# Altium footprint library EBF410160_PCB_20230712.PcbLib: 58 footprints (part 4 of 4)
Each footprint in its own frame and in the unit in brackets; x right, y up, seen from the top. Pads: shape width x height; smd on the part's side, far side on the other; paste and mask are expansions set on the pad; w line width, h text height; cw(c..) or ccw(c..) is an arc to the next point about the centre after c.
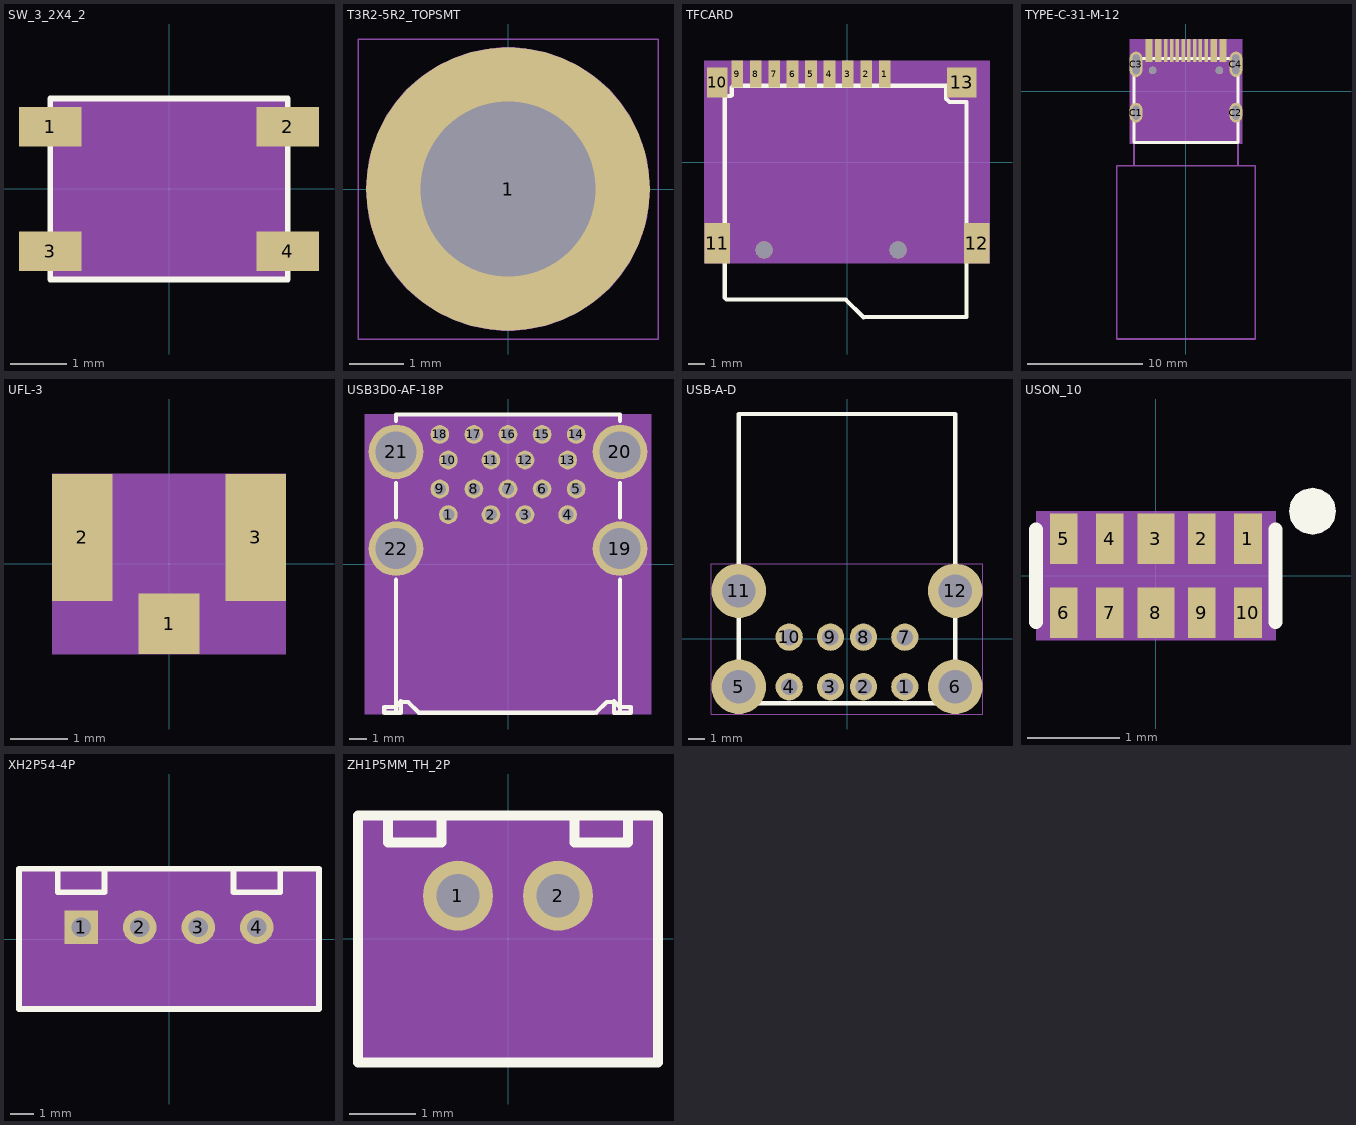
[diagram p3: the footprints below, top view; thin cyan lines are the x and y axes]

## SW_3_2X4_2 [mil] "SW_3_2X4_2"
pads (4):
  rect 43.31x27.56 smd: 1(-82.97,43) 2(82.39,43) 3(-82.97,-43.62) 4(82.39,-43.62)
Top Overlay:
  lines w3.94: -82.97,-63.3 -82.97,62.68 82.39,62.68 82.39,-63.3 -82.97,-63.3
Top 3D Body:
  region: -83.09,62.61 -83.09,-62.61 83.09,-62.61 83.09,62.61
Mechanical 20:
  text "2" at 82.39,55.8 h16
  text "1" at -82.97,55.8 h16
  text "4" at 82.39,-30.82 h16
  text "3" at -82.97,-30.82 h16
3D body: height 150, standoff 0, extent -83.09,-62.61 83.09,62.61

## T3R2-5R2_TOPSMT [mm] "T3R2-5R2_TOPSMT"
pads (1):
  round 5.2 hole 3.2: 1(0,0)
Top Overlay:
  text "M2X3mm" at -0.758,0.666 h0.3
Top Paste:
  dashed: 0.406,2.568 0.629,2.523 0.846,2.458 1.057,2.375 1.26,2.274 1.454,2.156 1.636,2.021 1.806,1.87 1.962,1.706 2.103,1.528 2.228,1.339 2.337,1.14 2.427,0.932 2.499,0.717 2.552,0.496 2.568,0.406 1.548,0.406 1.506,0.54 1.454,0.669 1.39,0.793 1.315,0.911 1.231,1.022 1.137,1.126 1.035,1.221 0.924,1.306 0.807,1.382 0.684,1.447 0.555,1.501 0.422,1.544 0.406,1.548
  dashed: 2.568,-0.406 2.523,-0.629 2.458,-0.846 2.375,-1.057 2.274,-1.26 2.156,-1.454 2.021,-1.636 1.87,-1.806 1.706,-1.962 1.528,-2.103 1.339,-2.228 1.14,-2.337 0.932,-2.427 0.717,-2.499 0.496,-2.552 0.406,-2.568 0.406,-1.548 0.54,-1.506 0.669,-1.454 0.793,-1.39 0.911,-1.315 1.022,-1.231 1.126,-1.137 1.221,-1.035 1.306,-0.924 1.382,-0.807 1.447,-0.684 1.501,-0.555 1.544,-0.422 1.548,-0.406
  dashed: -0.406,-2.568 -0.629,-2.523 -0.846,-2.458 -1.057,-2.375 -1.26,-2.274 -1.454,-2.156 -1.636,-2.021 -1.806,-1.87 -1.962,-1.706 -2.103,-1.528 -2.228,-1.339 -2.337,-1.14 -2.427,-0.932 -2.499,-0.717 -2.552,-0.496 -2.568,-0.406 -1.548,-0.406 -1.506,-0.54 -1.454,-0.669 -1.39,-0.793 -1.315,-0.911 -1.231,-1.022 -1.137,-1.126 -1.035,-1.221 -0.924,-1.306 -0.807,-1.382 -0.684,-1.447 -0.555,-1.501 -0.422,-1.544 -0.406,-1.548
  dashed: -2.568,0.406 -2.523,0.629 -2.458,0.846 -2.375,1.057 -2.274,1.26 -2.156,1.454 -2.021,1.636 -1.87,1.806 -1.706,1.962 -1.528,2.103 -1.339,2.228 -1.14,2.337 -0.932,2.427 -0.717,2.499 -0.496,2.552 -0.406,2.568 -0.406,1.548 -0.54,1.506 -0.669,1.454 -0.793,1.39 -0.911,1.315 -1.022,1.231 -1.126,1.137 -1.221,1.035 -1.306,0.924 -1.382,0.807 -1.447,0.684 -1.501,0.555 -1.544,0.422 -1.548,0.406
Top 3D Body:
  lines w0.025: -2.75,-2.75 -2.75,2.75 2.75,2.75 2.75,-2.75 -2.75,-2.75
Mechanical 20:
  text "1" at -0.12,0 h0.3
Top Assembly:
  circle w0.025: c0,0 r2.591

## TFCARD [mil] "TFCARD"
pads (15):
  rect 27.56x62.99 smd: 1(88.58,206.82) 2(45.27,206.82) 3(1.97,206.82) 4(-41.34,206.82) 5(-84.65,206.82) 6(-127.95,206.82) 7(-171.26,206.82) 8(-214.57,206.82) 9(-257.88,206.82)
  rect 47.24x70 smd: 10(-305.12,187.13)
  rect 60x95 smd: 11(-305.12,-190.81) 12(305.12,-190.81)
  rect 70x70 smd: 13(269.68,187.13)
  round 40 hole 40 unplated: ""(-194.88,-206.56) ""(120.08,-206.56)
Top Overlay:
  lines w10: -289.12,155.19 -273.12,155.19 -271.12,157.19 -271.12,175.19 -267.12,179.19 232.88,179.19 232.88,149.19 240.88,141.19 280.88,141.19 280.88,-364.05 38.88,-364.81 -3.12,-322.81 -283.12,-322.81 -287.12,-318.81 -287.12,153.19 -289.12,155.19
Top 3D Body:
  region: -335.12,-238.31 -335.12,238.31 335.12,238.31 335.12,-238.31
Mechanical 20:
  text "5" at -84.65,218.82 h30
  text "2" at 45.27,218.82 h30
  text "7" at -171.26,218.82 h30
  text "8" at -214.57,218.82 h30
  text "1" at 88.58,218.82 h30
  text "3" at 1.97,218.82 h30
  text "4" at -41.34,218.82 h30
  text "13" at 269.68,211.13 h30
  text "12" at 305.12,-166.81 h30
  text "11" at -305.12,-166.81 h30
  text "10" at -305.12,211.13 h30
  text "6" at -127.95,218.82 h30
  text "9" at -257.88,218.82 h30
3D body: height 150, standoff 0, extent -335.12,-238.31 335.12,238.31

## TYPE-C-31-M-12 [mm] "TYPE-C-31-M-12"
pads (22):
  rect 0.3x2 smd: A1(-3.35,3.539) A4(-2.55,3.539) A5(-1.25,3.539) A6(-0.249,3.539) A7(0.249,3.539) A8(1.25,3.539) A9(2.55,3.539) A12(3.35,3.539) B1(3.05,3.539) B4(2.25,3.539) B5(1.75,3.539) B6(0.749,3.539) B7(-0.749,3.539) B8(-1.75,3.539) B9(-2.25,3.539) B12(-3.05,3.539)
  oval 1.1x1.7 / inner round 1.524 / far side oval 1.1x1.7 hole 1.2 slot 0.6 at 0 deg: C1(-4.32,-1.84) C2(4.32,-1.84)
  oval 1.1x2.2 / inner round 1.524 / far side oval 1.1x2.2 hole 1.7 slot 0.6 at 0 deg: C3(-4.32,2.351) C4(4.32,2.351)
  round 0.65 hole 0.65 unplated: ""(-2.89,1.82) ""(2.89,1.82)
Top Overlay:
  lines w0.249: -4.501,-4.431 -4.501,2.861 4.501,2.861 4.501,-4.431 -4.501,-4.431
Top 3D Body:
  region: -4.869,-4.54 4.869,-4.54 4.869,4.54 -4.869,4.54
Mechanical 20:
  text "A1" at -3.046,3.539 h0.38
  text "B12" at -2.593,3.539 h0.38
  text "B1" at 3.355,3.539 h0.38
  text "A12" at 3.808,3.539 h0.38
  text "B7" at -0.445,3.539 h0.38
  text "A7" at 0.554,3.539 h0.38
  text "A6" at 0.056,3.539 h0.38
  text "B6" at 1.054,3.539 h0.38
  text "A4" at -2.245,3.539 h0.38
  text "B9" at -1.946,3.539 h0.38
  text "B4" at 2.555,3.539 h0.38
  text "A9" at 2.855,3.539 h0.38
  text "C1" at -4.016,-1.84 h0.38
  text "C3" at -4.016,2.351 h0.38
  text "C4" at 4.625,2.351 h0.38
  text "C2" at 4.625,-1.84 h0.38
  text "A5" at -0.945,3.539 h0.38
  text "B5" at 2.055,3.539 h0.38
  text "B8" at -1.445,3.539 h0.38
  text "A8" at 1.555,3.539 h0.38
Top Assembly:
  lines w0.15: -4.5,-4.44 -4.5,-6.431 ; 0,-6.431 6,-6.431 6,-21.431 -6,-21.431 -6,-6.431 -4.5,-6.431 ; 4.501,-4.431 4.501,-6.431 -4.5,-6.431
3D body: height 3.81, standoff 0, extent -4.869,-4.54 4.869,4.54

## UFL-3 [mm] "UFL-3"
pads (3):
  rect 1.05x1.05 smd: 1(0,-1.038)
  rect 1.05x2.2 smd: 2(-1.5,0.462) 3(1.5,0.462)
Top 3D Body:
  region: -2.025,-1.562 2.025,-1.562 2.025,1.562 -2.025,1.562
Mechanical 20:
  text "3" at 1.805,0.462 h0.76
  text "2" at -1.195,0.462 h0.76
  text "1" at 0.305,-1.038 h0.76
3D body: height 3.81, standoff 0, extent -2.025,-1.562 2.025,1.562

## USB3D0-AF-18P [mm] "USB3D0-AF-18P"
pads (22):
  round 1.1 / inner round 1.524 / far side round 1.1 hole 0.7: 1(-3.5,2.9) 2(-1,2.9) 3(1,2.9) 5(4,4.4) 6(2,4.4) 8(-2,4.4) 9(-4,4.4) 10(-3.5,6.1) 11(-1,6.1) 12(1,6.1) 14(4,7.6) 15(2,7.6) 17(-2,7.6) 18(-4,7.6)
  round 1.1 hole 0.7: 4(3.5,2.9) 7(0,4.4) 13(3.5,6.1) 16(0,7.6)
  round 3.2 hole 2.4: 19(6.57,0.9) 20(6.57,6.58) 21(-6.57,6.58) 22(-6.57,0.9)
Top Overlay:
  lines w0.254: -6.57,-8.74 -6.57,-0.931 ; -6.57,2.731 -6.57,4.749 ; -6.57,8.411 -6.57,8.774 6.57,8.774 6.57,8.411 ; -6.283,-8.057 -6.616,-8.39 -7.257,-8.39 -7.257,-8.72 -6.283,-8.72 -6.283,-8.093 -5.86,-8.093 -5.234,-8.72 5.067,-8.72 ; 5.168,-8.72 5.795,-8.093 6.217,-8.093 6.217,-8.72 7.192,-8.72 7.192,-8.39 6.551,-8.39 6.217,-8.057 ; 6.57,-8.74 6.57,-0.931 ; 6.57,2.731 6.57,4.749
Bottom Overlay:
  drawing of 19 lines, arcs and shapes, not listed
Top 3D Body:
  region: -8.4,8.8 -8.4,-8.8 8.4,-8.8 8.4,8.8
Mechanical 20:
  text "5" at 4.254,4.4 h0.64
  text "6" at 2.254,4.4 h0.64
  text "1" at -3.246,2.9 h0.64
  text "10" at -2.992,6.1 h0.64
  text "13" at 4.008,6.1 h0.64
  text "16" at 0.508,7.6 h0.64
  text "19" at 7.078,0.9 h0.64
  text "20" at 7.078,6.58 h0.64
  text "21" at -6.062,6.58 h0.64
  text "22" at -6.062,0.9 h0.64
  text "4" at 3.754,2.9 h0.64
  text "7" at 0.254,4.4 h0.64
  text "9" at -3.746,4.4 h0.64
  text "8" at -1.746,4.4 h0.64
  text "2" at -0.746,2.9 h0.64
  text "3" at 1.254,2.9 h0.64
  text "12" at 1.508,6.1 h0.64
  text "11" at -0.492,6.1 h0.64
  text "18" at -3.492,7.6 h0.64
  text "17" at -1.492,7.6 h0.64
  text "15" at 2.508,7.6 h0.64
  text "14" at 4.508,7.6 h0.64
3D body: height 3.81, standoff 0, extent -8.4,-8.8 8.4,8.8

## USB-A-D [mm] "USB-A-D"
pads (12):
  round 1.651 / inner round 1.524 / far side round 1.651 hole 1: 1(3.5,-2.9) 2(1,-2.9) 3(-1,-2.9) 7(3.5,0.1) 8(1,0.1) 9(-1,0.1)
  round 1.651 hole 1: 4(-3.5,-2.9) 10(-3.5,0.1)
  round 3.3 hole 2: 5(-6.55,-2.9) 6(6.55,-2.9) 11(-6.55,2.9) 12(6.55,2.9)
Top Overlay:
  lines w0.254: -6.55,-3.9 -6.55,13.6 6.55,13.6 6.55,-3.9 -6.55,-3.9
Bottom Overlay:
  drawing of 9 lines, arcs and shapes, not listed
Top 3D Body:
  lines w0.025: -8.2,-4.55 -8.2,4.55 8.2,4.55 8.2,-4.55 -8.2,-4.55
Mechanical 20:
  text "7" at 3.246,0.1 h0.64
  text "1" at 3.246,-2.9 h0.64
  text "4" at -3.754,-2.9 h0.64
  text "5" at -6.804,-2.9 h0.64
  text "6" at 6.296,-2.9 h0.64
  text "10" at -4.008,0.1 h0.64
  text "11" at -7.058,2.9 h0.64
  text "12" at 6.042,2.9 h0.64
  text "9" at -1.254,0.1 h0.64
  text "8" at 0.746,0.1 h0.64
  text "3" at -1.254,-2.9 h0.64
  text "2" at 0.746,-2.9 h0.64
Top Assembly:
  lines w0.025: -6.55,-3.9 -6.55,13.6 6.55,13.6 6.55,-3.9 -6.55,-3.9

## USON_10 [mm] "USON_10"
pads (10):
  rect 0.3x0.55 smd: 1(1,0.4) 2(0.5,0.4) 4(-0.5,0.4) 5(-1,0.4) 6(-1,-0.4) 7(-0.5,-0.4) 9(0.5,-0.4) 10(1,-0.4)
  rect 0.4x0.55 smd: 3(0,0.4) 8(0,-0.4)
Top Overlay:
  dashed: 1.955,0.7 1.935,0.602 1.88,0.52 1.798,0.465 1.7,0.445 1.602,0.465 1.575,0.483 1.52,0.52 1.465,0.602 1.445,0.7 1.465,0.798 1.52,0.88 1.575,0.917 1.602,0.935 1.7,0.955 1.798,0.935 1.88,0.88 1.935,0.798
  lines w0.15: -1.3,-0.5 -1.3,0.5 ; 1.3,-0.5 1.3,0.5
Top 3D Body:
  region: 1.3,0.7 1.3,-0.7 -1.3,-0.7 -1.3,0.7
Mechanical 20:
  text "3" at -0.254,0.4 h0.64
  text "8" at -0.254,-0.4 h0.64
  text "6" at -1.254,-0.4 h0.64
  text "5" at -1.254,0.4 h0.64
  text "4" at -0.754,0.4 h0.64
  text "7" at -0.754,-0.4 h0.64
  text "9" at 0.246,-0.4 h0.64
  text "2" at 0.246,0.4 h0.64
  text "10" at 0.492,-0.4 h0.64
  text "1" at 0.746,0.4 h0.64
3D body: height 3.81, standoff 0, extent -1.3,-0.7 1.3,0.7

## XH2P54-4P [mm] "XH2P54-4P"
pads (4):
  rect 1.45x1.45 / inner round 1.524 / far side rect 1.45x1.45 hole 0.85: 1(-3.81,0.508)
  round 1.45 / inner round 1.524 / far side round 1.45 hole 0.85: 2(-1.27,0.508) 3(1.27,0.508)
  round 1.45 hole 0.85: 4(3.81,0.508)
Top Overlay:
  lines w0.254: -6.51,-3.032 6.51,-3.032 6.51,3.048 -6.51,3.048 -6.51,-3.032 ; -4.826,2.032 -2.794,2.032 -2.794,3.048 -4.826,3.048 -4.826,2.032 ; 2.794,2.032 4.826,2.032 4.826,3.048 2.794,3.048 2.794,2.032
Bottom Overlay:
  lines w0.6: -2.54,-0.092 -2.54,1.108 ; 0,-0.092 0,1.108 ; 2.54,-0.092 2.54,1.108
Top 3D Body:
  region: -6.477,-3.048 6.477,-3.048 6.477,3.048 -6.477,3.048
Mechanical 20:
  text "3" at 1.27,0.762 h0.64
  text "2" at -1.27,0.762 h0.64
  text "4" at 3.81,0.762 h0.64
  text "1" at -3.81,0.762 h0.64
Top Assembly:
  lines w0.025: -6.477,-3.048 -6.477,3.048 6.51,3.048 6.51,-3.048 -6.477,-3.048
3D body: height 3.81, standoff 0, extent -6.477,-3.048 6.477,3.048

## ZH1P5MM_TH_2P [mm] "ZH1P5MM_TH_2P"
pads (2):
  round 1.05 / inner round 1.524 / far side round 1.05 hole 0.65: 1(-0.75,0.65)
  round 1.05 hole 0.65: 2(0.75,0.65)
Top Overlay:
  lines w0.15: -1.8,1.85 -1.8,1.45 -1,1.45 -1,1.85 ; 1,1.85 1,1.45 1.8,1.45 1.8,1.85 ; -2.25,-1.85 -2.25,1.85 2.25,1.85 2.25,-1.85 -2.25,-1.85
Bottom Overlay:
  lines w0.3: 0,-0.15 0,1.45 ; -1.5,-0.15 -1.3,-0.15 1.5,-0.15 1.5,1.45 -1.5,1.45 -1.5,-0.15
Top 3D Body:
  region: -2.2,-1.85 2.2,-1.85 2.2,1.85 -2.2,1.85
Mechanical 20:
  text "1" at -0.435,0.65 h0.79
  text "2" at 1.065,0.65 h0.79
3D body: height 3.81, standoff 0, extent -2.2,-1.85 2.2,1.85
